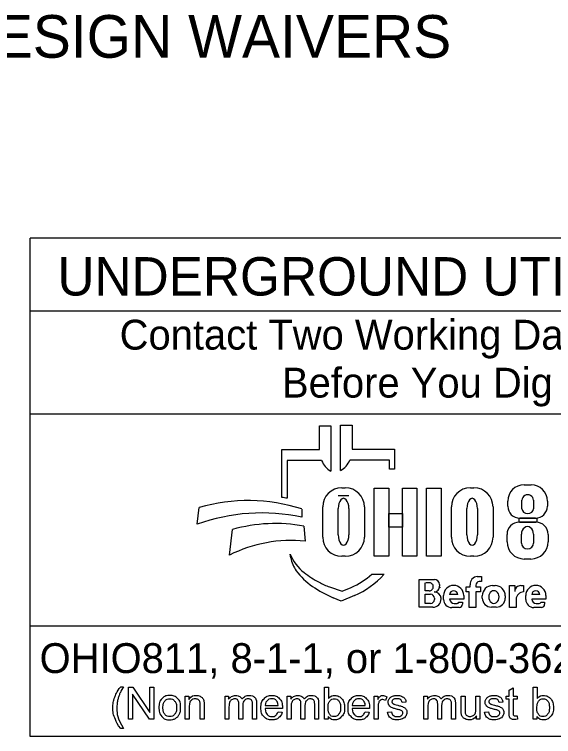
# Model space of a CAD drawing. Extents: x 0 to 40.9, y 0 to 22.
# Drawn here: x 2.904 to 5.431, y 2.143 to 5.529 of the extents above; entities that cross this region are included whole.
import ezdxf

# ---------------------------------------------------------------- set-up
doc = ezdxf.new("R2010")
doc.units = 0
doc.layers.add('SH_Border', color=7, linetype='Continuous')
doc.layers.add('SH_Cut_Line', color=7, linetype='Continuous')

msp = doc.modelspace()

# ---------------------------------------------------------------- linework, layer by layer
at = {"layer": 'SH_Border'}
for p, q in [((4.3335, 3.4883), (4.3335, 3.5998)), ((4.3335, 3.5998), (4.3872, 3.5998)), ((4.3872, 3.5998), (4.3872, 3.3877)), ((4.4329, 3.39), (4.4329, 3.6021)), ((4.4329, 3.6021), (4.4865, 3.6021)), ((4.4865, 3.6021), (4.4865, 3.4906)), ((4.1576, 3.2644), (4.1576, 3.4883)), ((4.1576, 3.4883), (4.3335, 3.4883)), ((4.4865, 3.4906), (4.6857, 3.4906)), ((4.6857, 3.4906), (4.6857, 3.3968)), ((4.1828, 3.4369), (4.1828, 3.26)), ((4.3439, 3.4369), (4.1828, 3.4369)), ((4.6625, 3.4392), (4.4761, 3.4392)), ((4.6625, 3.3968), (4.6625, 3.4392)), ((4.6857, 3.3968), (4.6625, 3.3968)), ((5.2931, 3.3231), (5.3258, 3.3231)), ((4.4385, 3.3091), (4.4551, 3.3091)), ((5.0416, 3.3091), (5.0581, 3.3091)), ((4.4718, 3.2721), (4.422, 3.2721)), ((5.283, 3.2111), (5.283, 3.2504)), ((5.3371, 3.2504), (5.3371, 3.2111)), ((4.3491, 3.0776), (4.3491, 3.2196)), ((4.5445, 3.2196), (4.5445, 3.0776)), ((4.9521, 3.0776), (4.9521, 3.2196)), ((5.1476, 3.2196), (5.1476, 3.0776)), ((5.2168, 3.2225), (5.2168, 3.2468)), ((5.4022, 3.2468), (5.4022, 3.2225)), ((3.7602, 3.1381), (3.7696, 3.2162)), ((4.2509, 3.2097), (4.2509, 3.1709)), ((4.422, 3.089), (4.422, 3.2114)), ((4.4718, 3.2114), (4.4718, 3.089)), ((5.025, 3.089), (5.025, 3.2114)), ((5.0748, 3.2114), (5.0748, 3.089)), ((5.3462, 3.1665), (5.2728, 3.1665)), ((4.2608, 3.1291), (4.2671, 3.0582)), ((5.271, 3.1482), (5.3483, 3.1482)), ((3.912, 2.9936), (3.9267, 3.1137)), ((5.2131, 3.0563), (5.2131, 3.0903)), ((5.2806, 3.0503), (5.2806, 3.0912)), ((5.3374, 3.0912), (5.3374, 3.0503)), ((5.4062, 3.0903), (5.4062, 3.0563)), ((4.1997, 2.9807), (4.1967, 2.9986)), ((4.4551, 2.9882), (4.4385, 2.9882)), ((5.0581, 2.9882), (5.0416, 2.9882)), ((5.3252, 2.9753), (5.2941, 2.9753)), ((4.58, 2.9048), (4.6375, 2.9048)), ((4.8013, 2.749), (4.8013, 2.8798)), ((4.8013, 2.8798), (4.8725, 2.8798)), ((5.0739, 2.8926), (5.0934, 2.8926)), ((5.0934, 2.8926), (5.0934, 2.8696)), ((4.3816, 2.8444), (4.441, 2.8239)), ((4.8293, 2.8263), (4.8293, 2.8632)), ((4.8545, 2.8632), (4.8332, 2.8632)), ((4.8963, 2.856), (4.8963, 2.8481)), ((5.0213, 2.8212), (5.0213, 2.8442)), ((5.0213, 2.8442), (5.0406, 2.8442)), ((5.0406, 2.8442), (5.0406, 2.8546)), ((5.0667, 2.8526), (5.0667, 2.8442)), ((5.0667, 2.8442), (5.0883, 2.8442)), ((5.0934, 2.8691), (5.0832, 2.8691)), ((5.0883, 2.8442), (5.0883, 2.8212)), ((5.1451, 2.8508), (5.1573, 2.8508)), ((5.2254, 2.7478), (5.2254, 2.8505)), ((5.2254, 2.8505), (5.2499, 2.8505)), ((5.2499, 2.8505), (5.2499, 2.8237)), ((5.2772, 2.8505), (5.291, 2.8505)), ((5.291, 2.8505), (5.291, 2.8209)), ((4.441, 2.8239), (4.4821, 2.8417)), ((4.8487, 2.8263), (4.8293, 2.8263)), ((5.0362, 2.8212), (5.0213, 2.8212)), ((5.0362, 2.7478), (5.0362, 2.8212)), ((5.0883, 2.8212), (5.0667, 2.8212)), ((5.0667, 2.8212), (5.0667, 2.7478)), ((4.435, 2.7769), (4.3976, 2.7934)), ((4.4983, 2.8044), (4.435, 2.7769)), ((4.8293, 2.7669), (4.8293, 2.8097)), ((4.8293, 2.8097), (4.8548, 2.8097)), ((4.8729, 2.7916), (4.8729, 2.7853)), ((4.9043, 2.7887), (4.9043, 2.7884)), ((4.9159, 2.7858), (4.9159, 2.8042)), ((4.9824, 2.8082), (4.9439, 2.8082)), ((5.0104, 2.7866), (4.944, 2.7866)), ((5.0104, 2.8042), (5.0104, 2.7866)), ((5.0973, 2.7922), (5.0973, 2.8029)), ((5.2051, 2.8029), (5.2051, 2.7922)), ((5.2559, 2.786), (5.2559, 2.7478)), ((5.3008, 2.7858), (5.3008, 2.8042)), ((5.3674, 2.8082), (5.3288, 2.8082)), ((5.3953, 2.7866), (5.3289, 2.7866)), ((5.3953, 2.8042), (5.3953, 2.7866)), ((4.865, 2.749), (4.8013, 2.749)), ((4.8546, 2.7669), (4.8293, 2.7669)), ((4.9892, 2.7478), (4.9538, 2.7478)), ((4.9649, 2.7673), (4.979, 2.7673)), ((4.9876, 2.7729), (5.0045, 2.7729)), ((5.0045, 2.7729), (5.0045, 2.7631)), ((5.0667, 2.7478), (5.0362, 2.7478)), ((5.1623, 2.7494), (5.1401, 2.7494)), ((5.2559, 2.7478), (5.2254, 2.7478)), ((5.3742, 2.7478), (5.3388, 2.7478)), ((5.3498, 2.7673), (5.3639, 2.7673)), ((5.3725, 2.7729), (5.3894, 2.7729)), ((5.3894, 2.7729), (5.3894, 2.7631))]:
    msp.add_line(p, q, dxfattribs=at)
for points in [[(4.591, 3.3081), (4.6589, 3.3081), (4.6589, 2.9881), (4.591, 2.9881)], [(4.7231, 3.3081), (4.7911, 3.3081), (4.7911, 2.9881), (4.7231, 2.9881)], [(4.8364, 3.3081), (4.9052, 3.3081), (4.9052, 2.9881), (4.8364, 2.9881)], [(4.6589, 3.1882), (4.7231, 3.1882), (4.7231, 3.1242), (4.6589, 3.1242)], [(5.2706, 3.1665), (5.3523, 3.1665), (5.3523, 3.1481), (5.2706, 3.1481)]]:
    msp.add_lwpolyline(points, close=True, dxfattribs=at)
for points in [[(3.4021, 2.3766), (3.4153, 2.3766)], [(3.4389, 2.2239), (3.4389, 2.3741), (3.4592, 2.3741), (3.5382, 2.2561), (3.5382, 2.3741), (3.5572, 2.3741), (3.5572, 2.2239), (3.5369, 2.2239), (3.4579, 2.3419), (3.4579, 2.2239), (3.4389, 2.2239)], [(4.3743, 2.2239), (4.3573, 2.2239), (4.3573, 2.3741), (4.3757, 2.3741), (4.3757, 2.3206)], [(5.2233, 2.2558), (5.2233, 2.3185), (5.2097, 2.3185), (5.2097, 2.3328), (5.2233, 2.3328), (5.2233, 2.3597), (5.2417, 2.3708), (5.2417, 2.3328), (5.2601, 2.3328), (5.2601, 2.3185), (5.2417, 2.3185), (5.2417, 2.2547)], [(5.3534, 2.2239), (5.3363, 2.2239), (5.3363, 2.3741), (5.3548, 2.3741), (5.3548, 2.3206)], [(3.7048, 2.2239), (3.7048, 2.3328), (3.7214, 2.3328), (3.7214, 2.3173)], [(3.8912, 2.2239), (3.8912, 2.3328), (3.9077, 2.3328), (3.9077, 2.3174)], [(4.1826, 2.2239), (4.1826, 2.3328), (4.1991, 2.3328), (4.1991, 2.3174)], [(4.5904, 2.2239), (4.5904, 2.3328), (4.607, 2.3328), (4.607, 2.3163)], [(4.6495, 2.3293), (4.643, 2.3122)], [(4.7394, 2.3046), (4.7213, 2.3022)], [(4.8236, 2.2239), (4.8236, 2.3328), (4.8401, 2.3328), (4.8401, 2.3174)], [(4.9979, 2.2654), (4.9979, 2.3328), (5.0164, 2.3328), (5.0164, 2.2724)], [(5.0676, 2.2745), (5.0676, 2.3328), (5.0861, 2.3328), (5.0861, 2.2239), (5.0696, 2.2239)], [(5.194, 2.3046), (5.1759, 2.3022)], [(3.7233, 2.2833), (3.7233, 2.2239), (3.7048, 2.2239)], [(3.7932, 2.2908), (3.7932, 2.2239), (3.7748, 2.2239), (3.7748, 2.2901)], [(3.9097, 2.2803), (3.9097, 2.2239), (3.8912, 2.2239)], [(3.9743, 2.2871), (3.9743, 2.2239), (3.9559, 2.2239), (3.9559, 2.2946)], [(4.0388, 2.2986), (4.0388, 2.2239), (4.0203, 2.2239), (4.0203, 2.2924)], [(4.16, 2.2736), (4.0788, 2.2736)], [(4.0799, 2.2887), (4.1406, 2.2887)], [(4.201, 2.2803), (4.201, 2.2239), (4.1826, 2.2239)], [(4.2657, 2.2871), (4.2657, 2.2239), (4.2473, 2.2239), (4.2473, 2.2946)], [(4.3301, 2.2986), (4.3301, 2.2239), (4.3117, 2.2239), (4.3117, 2.2924)], [(4.568, 2.2736), (4.4868, 2.2736)], [(4.4879, 2.2887), (4.5486, 2.2887)], [(4.6088, 2.2809), (4.6088, 2.2239), (4.5904, 2.2239)], [(4.842, 2.2803), (4.842, 2.2239), (4.8236, 2.2239)], [(4.9067, 2.2871), (4.9067, 2.2239), (4.8883, 2.2239), (4.8883, 2.2946)], [(4.9711, 2.2986), (4.9711, 2.2239), (4.9527, 2.2239), (4.9527, 2.2924)], [(4.1404, 2.2591), (4.1595, 2.2567)], [(4.3743, 2.2375), (4.3743, 2.2239)], [(4.5484, 2.2591), (4.5675, 2.2567)], [(4.653, 2.2564), (4.6712, 2.2593)], [(5.0696, 2.2239), (5.0696, 2.24)], [(5.1076, 2.2564), (5.1258, 2.2593)], [(5.2601, 2.2404), (5.2628, 2.2241)], [(5.3534, 2.2375), (5.3534, 2.2239)], [(3.4153, 2.1798), (3.4021, 2.1798)]]:
    msp.add_lwpolyline(points, dxfattribs=at)
for centre, radius, start, end in [((4.4353, 3.4736), 0.0985, 201.9296, 240.7469), ((4.3847, 3.476), 0.0985, 299.2531, 338.0704), ((5.2931, 3.2468), 0.0763, 90, 180), ((5.3258, 3.2468), 0.0763, 0, 90), ((4.4385, 3.2196), 0.0895, 90, 180), ((4.4551, 3.2196), 0.0895, 0, 90), ((5.0416, 3.2196), 0.0895, 90, 180), ((5.0581, 3.2196), 0.0895, 0, 90), ((4.0295, 2.4554), 0.8191, 79.2074, 81.0007), ((3.9997, 2.4302), 0.8191, 72.1402, 106.3144), ((5.2728, 3.2225), 0.056, 180, 270), ((5.3462, 3.2225), 0.056, 270, 0), ((4.0628, 2.2991), 0.8919, 77.8238, 109.8274), ((4.1267, 2.4094), 0.7322, 79.44, 105.8467), ((5.271, 3.0903), 0.0579, 90, 180), ((5.3483, 3.0903), 0.0579, 0, 90), ((4.1987, 2.4262), 0.6357, 83.8248, 116.8021), ((4.4385, 3.0776), 0.0895, 180, 270), ((4.4551, 3.0776), 0.0895, 270, 0), ((5.0416, 3.0776), 0.0895, 180, 270), ((5.0581, 3.0776), 0.0895, 270, 0), ((5.2941, 3.0563), 0.081, 180, 270), ((5.3252, 3.0563), 0.081, 270, 0), ((4.3841, 3.0707), 0.2008, 201.0457, 232.5314), ((4.341, 3.0048), 0.1433, 189.6817, 216.0884), ((4.4747, 3.1022), 0.3088, 216.0884, 235.7167), ((4.5766, 3.3219), 0.5173, 232.5314, 241.794), ((4.3387, 3.1722), 0.3602, 293.4582, 312.0712), ((4.3387, 3.1722), 0.401, 293.4582, 317.8286), ((4.8725, 2.856), 0.0238, 0, 90), ((5.0739, 2.859), 0.0335, 90, 187.5187), ((4.6412, 3.3465), 0.6044, 235.7167, 246.2325), ((4.4914, 3.1631), 0.3371, 241.794, 250.9821), ((4.8487, 2.845), 0.0187, 270, 2.0582), ((4.8505, 2.8463), 0.0169, 357.8325, 90), ((4.8721, 2.8453), 0.0243, 270, 6.6529), ((4.9631, 2.8042), 0.0473, 0, 180), ((5.0832, 2.8526), 0.0165, 90, 180), ((5.1451, 2.8029), 0.0478, 90, 180), ((5.1573, 2.8029), 0.0478, 0, 90), ((5.2768, 2.8237), 0.0269, 89.2449, 180), ((5.3481, 2.8042), 0.0473, 0, 180), ((4.8722, 2.7889), 0.0321, 4.0748, 90), ((4.8827, 2.8438), 0.0175, 347.4023, 0), ((4.9632, 2.8072), 0.0193, 2.9632, 177.0368), ((5.2908, 2.786), 0.0349, 89.6033, 180), ((5.3481, 2.8072), 0.0193, 2.9632, 177.0368), ((4.8546, 2.7853), 0.0184, 270, 0), ((4.8548, 2.7916), 0.0181, 0, 90), ((4.865, 2.7884), 0.0393, 270, 0), ((4.8714, 2.7887), 0.033, 0, 11.7502), ((4.9538, 2.7858), 0.038, 180, 270), ((4.9649, 2.7883), 0.021, 184.827, 270), ((5.1401, 2.7922), 0.0428, 180, 270), ((5.1623, 2.7922), 0.0428, 270, 0), ((5.3388, 2.7858), 0.038, 180, 270), ((5.3498, 2.7883), 0.021, 184.827, 270), ((4.979, 2.7767), 0.00938, 270, 335.9979), ((4.9892, 2.7631), 0.0152, 270, 0), ((5.3639, 2.7767), 0.00938, 270, 335.9979), ((5.3742, 2.7631), 0.0152, 270, 0)]:
    msp.add_arc(centre, radius, start, end, dxfattribs=at)
for centre, major_axis, ratio, start_param, end_param in [((4.4469, 3.2114), (0, 0.0484), 0.514403, 4.712389, 7.853982), ((5.0499, 3.2114), (0, 0.0484), 0.514403, 4.712389, 7.853982), ((5.31, 3.2504), (0.0271, 0), 0.969373, 0, 3.141593), ((5.31, 3.2111), (0.0271, 0), 0.818453, 3.141593, 6.283185), ((5.309, 3.0912), (0, 0.0358), 0.794529, 4.712389, 7.853982), ((4.4469, 3.089), (0, 0.0484), 0.514403, 1.570796, 4.712389), ((5.0499, 3.089), (0, 0.0484), 0.514403, 1.570796, 4.712389), ((5.309, 3.0503), (0.0284, 0), 0.959837, 3.141593, 6.283185), ((5.1517, 2.7976), (0, 0.029), 0.832186, 4.712389, 7.853982), ((5.1517, 2.7976), (0, 0.0302), 0.797287, 1.570796, 4.712389)]:
    msp.add_ellipse(centre, major_axis=major_axis, ratio=ratio, start_param=start_param, end_param=end_param, dxfattribs=at)
for points in [[(3.4021, 2.1798), (3.3869, 2.199), (3.3763, 2.2248), (3.3657, 2.2506), (3.3657, 2.2783), (3.3657, 2.3026), (3.3736, 2.325), (3.3829, 2.3509), (3.4021, 2.3766)], [(3.4153, 2.3766), (3.4029, 2.3553), (3.3989, 2.3462), (3.3927, 2.332), (3.3891, 2.3167), (3.3847, 2.2975), (3.3847, 2.2782), (3.3847, 2.2289), (3.4153, 2.1798)], [(3.5814, 2.2783), (3.5814, 2.3085), (3.5981, 2.3231), (3.6122, 2.3352), (3.6323, 2.3352), (3.6547, 2.3352), (3.669, 2.3205), (3.6832, 2.3058), (3.6832, 2.2799), (3.6832, 2.2589), (3.6769, 2.2469), (3.6706, 2.2348), (3.6586, 2.2282), (3.6466, 2.2215), (3.6323, 2.2215), (3.6095, 2.2215), (3.5954, 2.2362), (3.5814, 2.2508), (3.5814, 2.2783)], [(3.6003, 2.2783), (3.6003, 2.2574), (3.6094, 2.247), (3.6185, 2.2366), (3.6323, 2.2366), (3.646, 2.2366), (3.6551, 2.2471), (3.6642, 2.2575), (3.6642, 2.279), (3.6642, 2.2991), (3.6551, 2.3095), (3.6459, 2.3199), (3.6323, 2.3199), (3.6185, 2.3199), (3.6094, 2.3096), (3.6003, 2.2992), (3.6003, 2.2783)], [(3.7214, 2.3173), (3.7334, 2.3352), (3.756, 2.3352), (3.7659, 2.3352), (3.7741, 2.3316), (3.7823, 2.3281), (3.7864, 2.3224), (3.7905, 2.3166), (3.7922, 2.3087), (3.7932, 2.3036), (3.7932, 2.2908)], [(3.7748, 2.2901), (3.7748, 2.3013), (3.7726, 2.3069), (3.7705, 2.3125), (3.765, 2.3158), (3.7595, 2.3191), (3.7521, 2.3191), (3.7404, 2.3191), (3.7318, 2.3117), (3.7233, 2.3042), (3.7233, 2.2833)], [(3.9077, 2.3174), (3.9128, 2.3254), (3.9214, 2.3303), (3.9299, 2.3352), (3.9407, 2.3352), (3.9528, 2.3352), (3.9606, 2.3301), (3.9683, 2.3251), (3.9715, 2.3161), (3.9844, 2.3352), (4.0051, 2.3352), (4.0213, 2.3352), (4.03, 2.3262), (4.0388, 2.3172), (4.0388, 2.2986)], [(3.9559, 2.2946), (3.9559, 2.3069), (3.9514, 2.313), (3.9469, 2.3191), (3.9366, 2.3191), (3.9288, 2.3191), (3.9222, 2.315), (3.9156, 2.311), (3.9126, 2.3031), (3.9097, 2.2952), (3.9097, 2.2803)], [(4.0203, 2.2924), (4.0203, 2.3035), (4.0185, 2.3083), (4.0168, 2.3132), (4.012, 2.3162), (4.0073, 2.3191), (4.001, 2.3191), (3.9895, 2.3191), (3.9819, 2.3115), (3.9743, 2.3039), (3.9743, 2.2871)], [(4.1595, 2.2567), (4.155, 2.24), (4.1428, 2.2307), (4.1306, 2.2215), (4.1117, 2.2215), (4.0878, 2.2215), (4.0738, 2.2362), (4.0598, 2.2509), (4.0598, 2.2774), (4.0598, 2.3049), (4.074, 2.32), (4.0881, 2.3352), (4.1106, 2.3352), (4.1324, 2.3352), (4.1463, 2.3203), (4.1601, 2.3055), (4.1601, 2.2785), (4.1601, 2.2769), (4.16, 2.2736)], [(4.1406, 2.2887), (4.1394, 2.3025), (4.1337, 2.3094), (4.1249, 2.3201), (4.1108, 2.3201), (4.0981, 2.3201), (4.0894, 2.3115), (4.0808, 2.303), (4.0799, 2.2887)], [(4.1991, 2.3174), (4.2042, 2.3254), (4.2127, 2.3303), (4.2212, 2.3352), (4.2321, 2.3352), (4.2442, 2.3352), (4.2519, 2.3301), (4.2597, 2.3251), (4.2628, 2.3161), (4.2758, 2.3352), (4.2965, 2.3352), (4.3127, 2.3352), (4.3214, 2.3262), (4.3301, 2.3172), (4.3301, 2.2986)], [(4.2473, 2.2946), (4.2473, 2.3069), (4.2428, 2.313), (4.2383, 2.3191), (4.228, 2.3191), (4.2202, 2.3191), (4.2136, 2.315), (4.207, 2.311), (4.204, 2.3031), (4.201, 2.2952), (4.201, 2.2803)], [(4.3117, 2.2924), (4.3117, 2.3035), (4.3099, 2.3083), (4.3081, 2.3132), (4.3034, 2.3162), (4.2987, 2.3191), (4.2923, 2.3191), (4.2809, 2.3191), (4.2733, 2.3115), (4.2657, 2.3039), (4.2657, 2.2871)], [(4.3741, 2.2792), (4.3741, 2.2596), (4.3794, 2.2509), (4.3881, 2.2366), (4.4029, 2.2366), (4.415, 2.2366), (4.4238, 2.2471), (4.4326, 2.2576), (4.4326, 2.2784), (4.4326, 2.2998), (4.4241, 2.3099), (4.4157, 2.3201), (4.4038, 2.3201), (4.3917, 2.3201), (4.3829, 2.3096), (4.3741, 2.299), (4.3741, 2.2792)], [(4.3757, 2.3206), (4.3874, 2.3352), (4.4055, 2.3352), (4.4155, 2.3352), (4.4245, 2.3311), (4.4335, 2.3271), (4.4392, 2.3198), (4.445, 2.3124), (4.4483, 2.3021), (4.4516, 2.2918), (4.4516, 2.28), (4.4516, 2.252), (4.4378, 2.2368), (4.4239, 2.2215), (4.4046, 2.2215), (4.3853, 2.2215), (4.3743, 2.2375)], [(4.5675, 2.2567), (4.563, 2.24), (4.5508, 2.2307), (4.5386, 2.2215), (4.5196, 2.2215), (4.4958, 2.2215), (4.4818, 2.2362), (4.4678, 2.2509), (4.4678, 2.2774), (4.4678, 2.3049), (4.482, 2.32), (4.4961, 2.3352), (4.5186, 2.3352), (4.5404, 2.3352), (4.5543, 2.3203), (4.5681, 2.3055), (4.5681, 2.2785), (4.5681, 2.2769), (4.568, 2.2736)], [(4.5486, 2.2887), (4.5474, 2.3025), (4.5417, 2.3094), (4.5328, 2.3201), (4.5188, 2.3201), (4.5061, 2.3201), (4.4974, 2.3115), (4.4888, 2.303), (4.4879, 2.2887)], [(4.607, 2.3163), (4.6133, 2.3278), (4.6187, 2.3315), (4.6241, 2.3352), (4.6305, 2.3352), (4.6398, 2.3352), (4.6495, 2.3293)], [(4.643, 2.3122), (4.6363, 2.3162), (4.6295, 2.3162), (4.6235, 2.3162), (4.6187, 2.3125), (4.6139, 2.3089), (4.6119, 2.3024), (4.6088, 2.2926), (4.6088, 2.2809)], [(4.7213, 2.3022), (4.7201, 2.3106), (4.7142, 2.3153), (4.7083, 2.3201), (4.6975, 2.3201), (4.6848, 2.3201), (4.6794, 2.3159), (4.6739, 2.3116), (4.6739, 2.306), (4.6739, 2.3024), (4.6762, 2.2995), (4.6785, 2.2966), (4.6833, 2.2946), (4.686, 2.2936), (4.6996, 2.2899), (4.7192, 2.2847), (4.7269, 2.2813), (4.7347, 2.278), (4.7391, 2.2717), (4.7435, 2.2653), (4.7435, 2.2559), (4.7435, 2.2467), (4.7381, 2.2386), (4.7327, 2.2304), (4.7226, 2.226), (4.7124, 2.2215), (4.6996, 2.2215), (4.6784, 2.2215), (4.6672, 2.2303), (4.6561, 2.2391), (4.653, 2.2564)], [(4.6712, 2.2593), (4.6727, 2.2483), (4.6798, 2.2425), (4.6868, 2.2366), (4.6995, 2.2366), (4.7122, 2.2366), (4.7184, 2.2418), (4.7245, 2.247), (4.7245, 2.254), (4.7245, 2.2602), (4.7191, 2.2638), (4.7153, 2.2663), (4.7002, 2.2701), (4.6799, 2.2752), (4.672, 2.2789), (4.6642, 2.2827), (4.6601, 2.2893), (4.6561, 2.2959), (4.6561, 2.3038), (4.6561, 2.3111), (4.6594, 2.3173), (4.6628, 2.3235), (4.6685, 2.3276), (4.6728, 2.3308), (4.6803, 2.333), (4.6877, 2.3352), (4.6962, 2.3352), (4.709, 2.3352), (4.7187, 2.3315), (4.7284, 2.3278), (4.733, 2.3215), (4.7377, 2.3152), (4.7394, 2.3046)], [(4.8401, 2.3174), (4.8452, 2.3254), (4.8537, 2.3303), (4.8622, 2.3352), (4.8731, 2.3352), (4.8852, 2.3352), (4.8929, 2.3301), (4.9007, 2.3251), (4.9038, 2.3161), (4.9168, 2.3352), (4.9375, 2.3352), (4.9537, 2.3352), (4.9624, 2.3262), (4.9711, 2.3172), (4.9711, 2.2986)], [(4.8883, 2.2946), (4.8883, 2.3069), (4.8838, 2.313), (4.8793, 2.3191), (4.869, 2.3191), (4.8612, 2.3191), (4.8546, 2.315), (4.848, 2.311), (4.845, 2.3031), (4.842, 2.2952), (4.842, 2.2803)], [(4.9527, 2.2924), (4.9527, 2.3035), (4.9509, 2.3083), (4.9491, 2.3132), (4.9444, 2.3162), (4.9397, 2.3191), (4.9333, 2.3191), (4.9219, 2.3191), (4.9143, 2.3115), (4.9067, 2.3039), (4.9067, 2.2871)], [(5.1759, 2.3022), (5.1747, 2.3106), (5.1688, 2.3153), (5.1629, 2.3201), (5.1521, 2.3201), (5.1394, 2.3201), (5.1339, 2.3159), (5.1285, 2.3116), (5.1285, 2.306), (5.1285, 2.3024), (5.1308, 2.2995), (5.133, 2.2966), (5.1378, 2.2946), (5.1406, 2.2936), (5.1542, 2.2899), (5.1737, 2.2847), (5.1815, 2.2813), (5.1893, 2.278), (5.1937, 2.2717), (5.1981, 2.2653), (5.1981, 2.2559), (5.1981, 2.2467), (5.1927, 2.2386), (5.1873, 2.2304), (5.1772, 2.226), (5.167, 2.2215), (5.1542, 2.2215), (5.1329, 2.2215), (5.1218, 2.2303), (5.1107, 2.2391), (5.1076, 2.2564)], [(5.1258, 2.2593), (5.1273, 2.2483), (5.1343, 2.2425), (5.1414, 2.2366), (5.154, 2.2366), (5.1668, 2.2366), (5.1729, 2.2418), (5.1791, 2.247), (5.1791, 2.254), (5.1791, 2.2602), (5.1736, 2.2638), (5.1698, 2.2663), (5.1548, 2.2701), (5.1345, 2.2752), (5.1266, 2.2789), (5.1188, 2.2827), (5.1147, 2.2893), (5.1107, 2.2959), (5.1107, 2.3038), (5.1107, 2.3111), (5.114, 2.3173), (5.1173, 2.3235), (5.1231, 2.3276), (5.1274, 2.3308), (5.1348, 2.333), (5.1423, 2.3352), (5.1508, 2.3352), (5.1636, 2.3352), (5.1733, 2.3315), (5.183, 2.3278), (5.1876, 2.3215), (5.1922, 2.3152), (5.194, 2.3046)], [(5.3532, 2.2792), (5.3532, 2.2596), (5.3585, 2.2509), (5.3672, 2.2366), (5.382, 2.2366), (5.3941, 2.2366), (5.4029, 2.2471), (5.4116, 2.2576), (5.4116, 2.2784), (5.4116, 2.2998), (5.4032, 2.3099), (5.3948, 2.3201), (5.3828, 2.3201), (5.3708, 2.3201), (5.362, 2.3096), (5.3532, 2.299), (5.3532, 2.2792)], [(5.3548, 2.3206), (5.3664, 2.3352), (5.3846, 2.3352), (5.3946, 2.3352), (5.4036, 2.3311), (5.4125, 2.3271), (5.4183, 2.3198), (5.4241, 2.3124), (5.4274, 2.3021), (5.4306, 2.2918), (5.4306, 2.28), (5.4306, 2.252), (5.4168, 2.2368), (5.403, 2.2215), (5.3836, 2.2215), (5.3644, 2.2215), (5.3534, 2.2375)], [(4.0788, 2.2736), (4.0799, 2.2557), (4.089, 2.2462), (4.0981, 2.2366), (4.1117, 2.2366), (4.1219, 2.2366), (4.1291, 2.242), (4.1362, 2.2473), (4.1404, 2.2591)], [(4.4868, 2.2736), (4.4879, 2.2557), (4.497, 2.2462), (4.5061, 2.2366), (4.5197, 2.2366), (4.5299, 2.2366), (4.537, 2.242), (4.5442, 2.2473), (4.5484, 2.2591)], [(5.0164, 2.2724), (5.0164, 2.258), (5.0175, 2.253), (5.0192, 2.2457), (5.0249, 2.2416), (5.0305, 2.2374), (5.0388, 2.2374), (5.0471, 2.2374), (5.0543, 2.2417), (5.0616, 2.2459), (5.0646, 2.2533), (5.0676, 2.2606), (5.0676, 2.2745)], [(5.0696, 2.24), (5.0569, 2.2215), (5.0351, 2.2215), (5.0255, 2.2215), (5.0171, 2.2252), (5.0088, 2.2289), (5.0047, 2.2345), (5.0007, 2.2401), (4.9991, 2.2482), (4.9979, 2.2536), (4.9979, 2.2654)], [(5.2628, 2.2241), (5.255, 2.2224), (5.2488, 2.2224), (5.2388, 2.2224), (5.2333, 2.2256), (5.2278, 2.2288), (5.2255, 2.234), (5.2233, 2.2392), (5.2233, 2.2558)], [(5.2417, 2.2547), (5.2417, 2.2468), (5.2427, 2.2445), (5.2436, 2.2423), (5.2458, 2.2409), (5.248, 2.2396), (5.2521, 2.2396), (5.2551, 2.2396), (5.2601, 2.2404)]]:
    msp.add_open_spline(points, degree=3, dxfattribs=at)
at = {"layer": 'SH_Cut_Line'}
for p, q in [((2.9775, 2.1428), (2.9775, 4.4803)), ((7.2275, 4.4803), (2.9775, 4.4803)), ((2.9775, 4.1387), (7.2275, 4.1387)), ((2.9775, 3.6553), (7.2275, 3.6553)), ((7.2275, 2.6607), (2.9775, 2.6607)), ((7.2275, 2.1428), (2.9775, 2.1428))]:
    msp.add_line(p, q, dxfattribs=at)

# ---------------------------------------------------------------- texts
at = {"layer": 'SH_Border'}
for s, height, p in [('ADA DESIGN WAIVERS', 0.2, (1.9944, 5.3256)), ('UNDERGROUND UTILITIES', 0.18, (3.1057, 4.2106)), ('Contact Two Working Days', 0.14, (3.3972, 3.9571)), ('Before You Dig', 0.14, (4.1583, 3.7321)), ('OHIO811, 8-1-1, or 1-800-362-2764', 0.14, (3.022, 2.4406))]:
    msp.add_text(s, height=height, dxfattribs=at).set_placement(p)

doc.saveas('drawing.dxf')
